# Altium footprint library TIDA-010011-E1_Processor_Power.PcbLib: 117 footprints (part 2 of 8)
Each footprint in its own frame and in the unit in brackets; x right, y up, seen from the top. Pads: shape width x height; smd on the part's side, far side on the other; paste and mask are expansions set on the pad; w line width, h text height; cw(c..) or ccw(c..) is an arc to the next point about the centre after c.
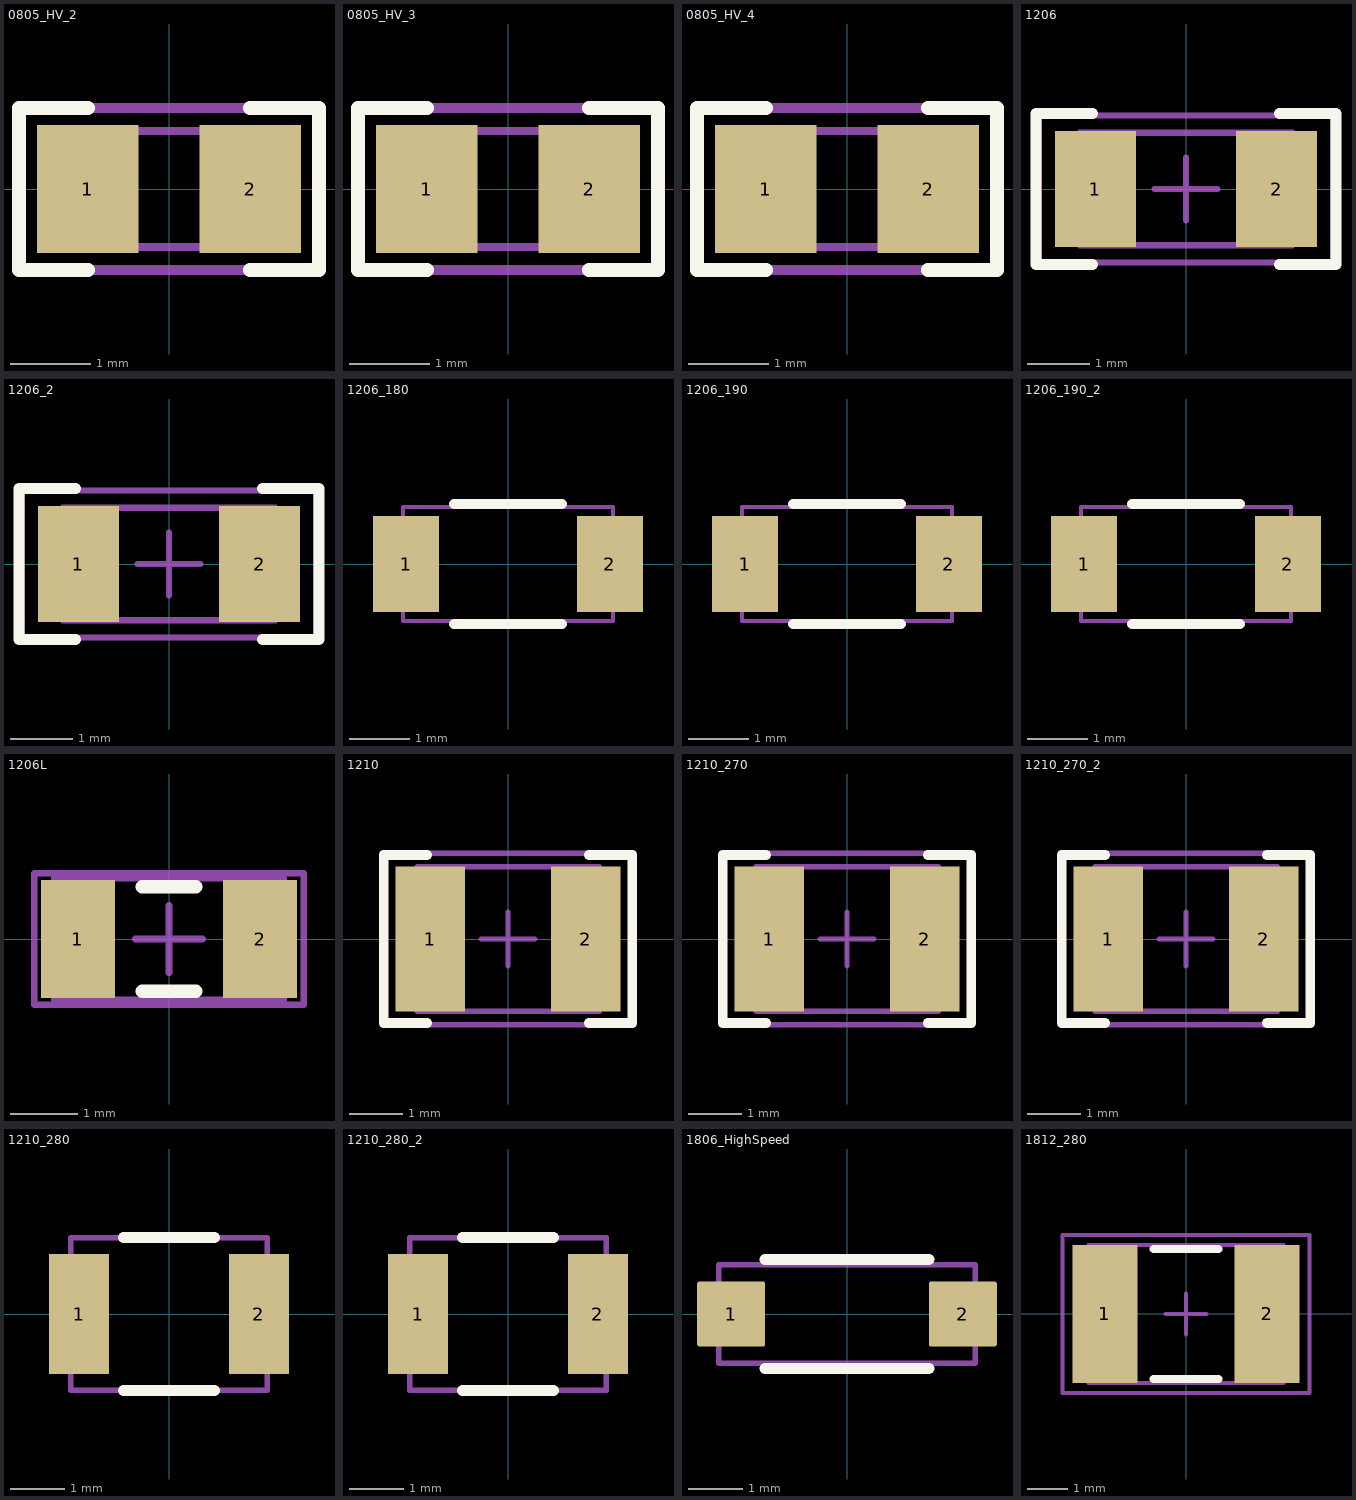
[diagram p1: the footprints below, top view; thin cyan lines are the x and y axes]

## 0805_HV_2 [mil]
pads (2):
  rect 50x63 smd: 1(-40,0) 2(40,0)
Top Overlay:
  lines w7: -40,-40 -74,-40 -74,0 -74,40 -40,40 ; 40,-40 74,-40 74,0 74,40 40,40
Mechanical 5:
  lines w5: -74,-40 74,-40 74,40 -74,40 -74,-40
  text ".Designator" at -37,-15 h20
Mechanical 13:
  lines w3.94: -25.59,-28.54 -25.59,28.54 ; 25.59,-28.54 25.59,28.54 ; -43.31,-28.54 43.31,-28.54 43.31,28.54 -43.31,28.54 -43.31,-28.54
3D body: height 57.09, standoff 0, extent -43.29,-28.52 -25.61,28.52
3D body: height 57.09, standoff 0, extent -25.57,-28.52 25.57,28.52
3D body: height 57.09, standoff 0, extent 25.61,-28.52 43.29,28.52

## 0805_HV_3 [mil]
pads (2):
  rect 50x63 smd: 1(-40,0) 2(40,0)
Top Overlay:
  lines w7: -40,-40 -74,-40 -74,0 -74,40 -40,40 ; 40,-40 74,-40 74,0 74,40 40,40
Mechanical 5:
  lines w5: -74,-40 74,-40 74,40 -74,40 -74,-40
  text ".Designator" at 30.94,8.8 h20
Mechanical 13:
  lines w3.94: -25.59,-28.54 -25.59,28.54 ; 25.59,-28.54 25.59,28.54 ; -43.31,-28.54 43.31,-28.54 43.31,28.54 -43.31,28.54 -43.31,-28.54
3D body: height 57.09, standoff 0, extent -43.29,-28.52 -25.61,28.52
3D body: height 57.09, standoff 0, extent -25.57,-28.52 25.57,28.52
3D body: height 57.09, standoff 0, extent 25.61,-28.52 43.29,28.52

## 0805_HV_4 [mil]
pads (2):
  rect 50x63 smd: 1(-40,0) 2(40,0)
Top Overlay:
  lines w7: -40,-40 -74,-40 -74,0 -74,40 -40,40 ; 40,-40 74,-40 74,0 74,40 40,40
Mechanical 5:
  lines w5: -74,-40 -74,40 74,40 74,-40 -74,-40
  text ".Designator" at -34,-6 h20
Mechanical 13:
  lines w3.94: -25.59,-28.54 -25.59,28.54 ; 25.59,-28.54 25.59,28.54 ; -43.31,-28.54 -43.31,28.54 43.31,28.54 43.31,-28.54 -43.31,-28.54
3D body: height 57.09, standoff 0, extent 25.61,-28.52 43.29,28.52
3D body: height 57.09, standoff 0, extent -25.57,-28.52 25.57,28.52
3D body: height 57.09, standoff 0, extent -43.29,-28.52 -25.61,28.52

## 1206 [mm] "1206 from SM-752 data"
height 1.35
pads (2):
  rect 1.3x1.85 smd: 1(-1.45,0) 2(1.45,0)
Top Overlay:
  lines w0.178: -1.5,-1.21 -2.4,-1.21 -2.4,1.21 -1.5,1.21 ; 1.5,-1.21 2.4,-1.21 2.4,1.21 1.5,1.21
Mechanical 5:
  lines w0.1: -1.7,-0.9 -1.7,0.9 1.7,0.9 1.7,-0.9 -1.7,-0.9
  text ".Designator" at -1.475,-0.4 h0.51
Mechanical 13:
  lines w0.1: -1.2,-0.9 -1.2,0.9 ; 1.2,-0.9 1.2,0.9 ; -1.7,-0.9 -1.7,0.9 1.7,0.9 1.7,-0.9 -1.7,-0.9
Mechanical 15:
  lines w0.1: -0.5,0 0.5,0 ; 0,-0.5 0,0.5 ; -2.35,-1.175 -2.35,1.175 2.35,1.175 2.35,-1.175 -2.35,-1.175
3D body: height 1.35, standoff 0, extent 1.201,-0.899 1.699,0.899
3D body: height 1.35, standoff 0, extent -1.199,-0.899 1.199,0.899
3D body: height 1.35, standoff 0, extent -1.699,-0.899 -1.201,0.899

## 1206_2 [mm]
pads (2):
  rect 1.3x1.85 smd: 1(-1.45,0) 2(1.45,0)
Top Overlay:
  lines w0.178: -1.5,-1.21 -2.4,-1.21 -2.4,1.21 -1.5,1.21 ; 1.5,-1.21 2.4,-1.21 2.4,1.21 1.5,1.21
Mechanical 5:
  lines w0.1: -1.7,-0.9 -1.7,0.9 1.7,0.9 1.7,-0.9 -1.7,-0.9
  text ".Designator" at -0.737,-0.305 h0.51
Mechanical 13:
  lines w0.1: -1.2,-0.9 -1.2,0.9 ; 1.2,-0.9 1.2,0.9 ; -1.7,-0.9 -1.7,0.9 1.7,0.9 1.7,-0.9 -1.7,-0.9
Mechanical 15:
  lines w0.1: -0.5,0 0.5,0 ; 0,-0.5 0,0.5 ; -2.35,-1.175 -2.35,1.175 2.35,1.175 2.35,-1.175 -2.35,-1.175
3D body: height 1.35, standoff 0, extent 1.201,-0.899 1.699,0.899
3D body: height 1.35, standoff 0, extent -1.199,-0.899 1.199,0.899
3D body: height 1.35, standoff 0, extent -1.699,-0.899 -1.201,0.899

## 1206_180 [mm] "1206_180"
height 1.8
pads (2):
  rect 1.1x1.6 smd: 1(-1.7,0) 2(1.7,0)
Top Overlay:
  lines w0.17: -0.9,-1 0.9,-1 ; -0.9,1 0.9,1
Mechanical 5:
  lines w0.07: -1.75,-0.95 -1.75,0.95 1.75,0.95 1.75,-0.95 -1.75,-0.95
  text ".Designator" at -1.092,-0.152 h0.51
3D body: height 1.8, standoff 0, extent 1.301,-0.949 1.749,0.949
3D body: height 1.8, standoff 0, extent -1.299,-0.949 1.299,0.949
3D body: height 1.8, standoff 0, extent -1.749,-0.949 -1.301,0.949

## 1206_190 [mm] "1206_190"
height 1.9
pads (2):
  rect 1.1x1.6 smd: 1(-1.7,0) 2(1.7,0)
Top Overlay:
  lines w0.17: -0.9,-1 0.9,-1 ; -0.9,1 0.9,1
Mechanical 5:
  lines w0.07: -1.75,-0.95 1.75,-0.95 1.75,0.95 -1.75,0.95 -1.75,-0.95
  text ".Designator" at 0.779,0.127 h0.51
3D body: height 1.9, standoff 0, extent -1.749,-0.949 -1.301,0.949
3D body: height 1.9, standoff 0, extent -1.299,-0.949 1.299,0.949
3D body: height 1.9, standoff 0, extent 1.301,-0.949 1.749,0.949

## 1206_190_2 [mm]
pads (2):
  rect 1.1x1.6 smd: 1(-1.7,0) 2(1.7,0)
Top Overlay:
  lines w0.17: -0.9,-1 0.9,-1 ; -0.9,1 0.9,1
Mechanical 5:
  lines w0.07: -1.75,-0.95 1.75,-0.95 1.75,0.95 -1.75,0.95 -1.75,-0.95
  text ".Designator" at 0.94,0.279 h0.51
3D body: height 1.9, standoff 0, extent -1.749,-0.949 -1.301,0.949
3D body: height 1.9, standoff 0, extent -1.299,-0.949 1.299,0.949
3D body: height 1.9, standoff 0, extent 1.301,-0.949 1.749,0.949

## 1206L [mm] "1206 from SM-752 data"
height 1.35
pads (2):
  rect 1.1x1.75 smd: 1(-1.35,0) 2(1.35,0)
Top Overlay:
  lines w0.2: -0.4,-0.775 0.4,-0.775 ; -0.4,0.775 0.4,0.775
Mechanical 5:
  lines w0.1: -1.7,-0.9 -1.7,0.9 1.7,0.9 1.7,-0.9 -1.7,-0.9
  text ".Designator" at -0.638,-0.372 h0.51
Mechanical 13:
  lines w0.1: -1.2,-0.9 -1.2,0.9 ; 1.2,-0.9 1.2,0.9 ; -1.7,-0.9 1.7,-0.9 1.7,0.9 -1.7,0.9 -1.7,-0.9
Mechanical 15:
  lines w0.1: -0.5,0 0.5,0 ; 0,-0.5 0,0.5 ; -2,-0.975 -2,0.975 2,0.975 2,-0.975 -2,-0.975
3D body: height 1.35, standoff 0, extent -1.699,-0.899 -1.201,0.899
3D body: height 1.35, standoff 0, extent -1.199,-0.899 1.199,0.899
3D body: height 1.35, standoff 0, extent 1.201,-0.899 1.699,0.899

## 1210 [mm] "1210 from SM-752 data"
height 1.35
pads (2):
  rect 1.3x2.7 smd: 1(-1.45,0) 2(1.45,0)
Top Overlay:
  lines w0.178: -1.511,-1.568 -2.316,-1.568 -2.316,1.568 -1.511,1.568 ; 1.511,-1.568 2.316,-1.568 2.316,1.568 1.511,1.568
Mechanical 5:
  lines w0.1: -1.7,-1.35 -1.7,1.35 1.7,1.35 1.7,-1.35 -1.7,-1.35
  text ".Designator" at 0.762,0.178 h0.51
Mechanical 13:
  lines w0.1: -1.2,-1.35 -1.2,1.35 ; 1.2,-1.35 1.2,1.35 ; -1.7,-1.35 1.7,-1.35 1.7,1.35 -1.7,1.35 -1.7,-1.35
Mechanical 15:
  lines w0.1: -0.5,0 0.5,0 ; 0,-0.5 0,0.5 ; -2.35,-1.6 2.35,-1.6 2.35,1.6 -2.35,1.6 -2.35,-1.6
3D body: height 1.35, standoff 0, extent 1.201,-1.349 1.699,1.349
3D body: height 1.35, standoff 0, extent -1.199,-1.349 1.199,1.349
3D body: height 1.35, standoff 0, extent -1.699,-1.349 -1.201,1.349

## 1210_270 [mm] "1210"
height 2.7
pads (2):
  rect 1.3x2.7 smd: 1(-1.45,0) 2(1.45,0)
Top Overlay:
  lines w0.178: -1.511,-1.568 -2.316,-1.568 -2.316,1.568 -1.511,1.568 ; 1.511,-1.568 2.316,-1.568 2.316,1.568 1.511,1.568
Mechanical 5:
  lines w0.1: -1.7,-1.35 -1.7,1.35 1.7,1.35 1.7,-1.35 -1.7,-1.35
  text ".Designator" at -0.832,-0.381 h0.51
Mechanical 13:
  lines w0.1: -1.2,-1.35 -1.2,1.35 ; 1.2,-1.35 1.2,1.35 ; -1.7,-1.35 1.7,-1.35 1.7,1.35 -1.7,1.35 -1.7,-1.35
Mechanical 15:
  lines w0.1: -0.5,0 0.5,0 ; 0,-0.5 0,0.5 ; -2.35,-1.6 2.35,-1.6 2.35,1.6 -2.35,1.6 -2.35,-1.6
3D body: height 2.7, standoff 0, extent 1.201,-1.349 1.699,1.349
3D body: height 2.7, standoff 0, extent -1.199,-1.349 1.199,1.349
3D body: height 2.7, standoff 0, extent -1.699,-1.349 -1.201,1.349

## 1210_270_2 [mm]
pads (2):
  rect 1.3x2.7 smd: 1(-1.45,0) 2(1.45,0)
Top Overlay:
  lines w0.178: -1.511,-1.568 -2.316,-1.568 -2.316,1.568 -1.511,1.568 ; 1.511,-1.568 2.316,-1.568 2.316,1.568 1.511,1.568
Mechanical 5:
  lines w0.1: -1.7,-1.35 1.7,-1.35 1.7,1.35 -1.7,1.35 -1.7,-1.35
  text ".Designator" at -0.991,-0.152 h0.51
Mechanical 13:
  lines w0.1: -1.2,-1.35 -1.2,1.35 ; 1.2,-1.35 1.2,1.35 ; -1.7,-1.35 -1.7,1.35 1.7,1.35 1.7,-1.35 -1.7,-1.35
Mechanical 15:
  lines w0.1: -0.5,0 0.5,0 ; 0,-0.5 0,0.5 ; -2.35,-1.6 -2.35,1.6 2.35,1.6 2.35,-1.6 -2.35,-1.6
3D body: height 2.7, standoff 0, extent -1.699,-1.349 -1.201,1.349
3D body: height 2.7, standoff 0, extent -1.199,-1.349 1.199,1.349
3D body: height 2.7, standoff 0, extent 1.201,-1.349 1.699,1.349

## 1210_280 [mm] "SMD, 2-Leads, Body 3.6x2.8mm, Height 2.8mm"
height 2.8
pads (2):
  rect 1.1x2.2 smd: 1(-1.65,0) 2(1.65,0)
Top Overlay:
  lines w0.2: -0.835,-1.4 0.835,-1.4 ; -0.835,1.4 0.835,1.4
Mechanical 5:
  lines w0.1: -1.8,-1.4 1.8,-1.4 1.8,1.4 -1.8,1.4 -1.8,-1.4
  text ".Designator" at -0.654,-0.307 h0.51
3D body: height 2.8, standoff 0, extent 1.6,-1.4 1.8,1.4
3D body: height 2.8, standoff 0, extent -1.6,-1.4 1.6,1.4
3D body: height 2.8, standoff 0, extent -1.8,-1.4 -1.6,1.4

## 1210_280_2 [mm]
pads (2):
  rect 1.1x2.2 smd: 1(-1.65,0) 2(1.65,0)
Top Overlay:
  lines w0.2: -0.835,-1.4 0.835,-1.4 ; -0.835,1.4 0.835,1.4
Mechanical 5:
  lines w0.1: -1.8,-1.4 1.8,-1.4 1.8,1.4 -1.8,1.4 -1.8,-1.4
  text ".Designator" at 0.152,-0.711 h0.51
3D body: height 2.8, standoff 0, extent 1.6,-1.4 1.8,1.4
3D body: height 2.8, standoff 0, extent -1.6,-1.4 1.6,1.4
3D body: height 2.8, standoff 0, extent -1.8,-1.4 -1.6,1.4

## 1806_HighSpeed [mm] "Wurth recommended land pattern"
height 1.85
pads (2):
  rrect8% 1.25x1.2 smd: 1(-2.125,0) 2(2.125,0)
Top Overlay:
  lines w0.2: -1.5,-1 1.5,-1 ; -1.5,1 1.5,1
Mechanical 5:
  lines w0.1: -2.35,-0.9 -2.35,0.9 2.35,0.9 2.35,-0.9 -2.35,-0.9
  text ".Designator" at -0.152,-0.356 h0.51
3D body "1806.stp": height 1.61, standoff 0.01, extent -2.25,-0.8 2.25,0.8

## 1812_280 [mm] "1812"
height 2.8
pads (2):
  rect 1.6x3.4 smd: 1(-2,0) 2(2,0)
Top Overlay:
  lines w0.2: -0.8,-1.6 0.8,-1.6 ; -0.8,1.6 0.8,1.6
Mechanical 5:
  lines w0.1: -2.4,-1.7 -2.4,1.7 2.4,1.7 2.4,-1.7 -2.4,-1.7
  text ".Designator" at -0.279,-0.813 h0.51
Mechanical 13:
  lines w0.1: -1.9,-1.7 -1.9,1.7 ; 1.9,-1.7 1.9,1.7 ; -2.4,-1.7 2.4,-1.7 2.4,1.7 -2.4,1.7 -2.4,-1.7
Mechanical 15:
  lines w0.1: -0.5,0 0.5,0 ; 0,-0.5 0,0.5 ; -3.05,-1.95 3.05,-1.95 3.05,1.95 -3.05,1.95 -3.05,-1.95
3D body: height 2.8, standoff 0, extent 1.901,-1.699 2.399,1.699
3D body: height 2.8, standoff 0, extent -1.899,-1.699 1.899,1.699
3D body: height 2.8, standoff 0, extent -2.399,-1.699 -1.901,1.699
